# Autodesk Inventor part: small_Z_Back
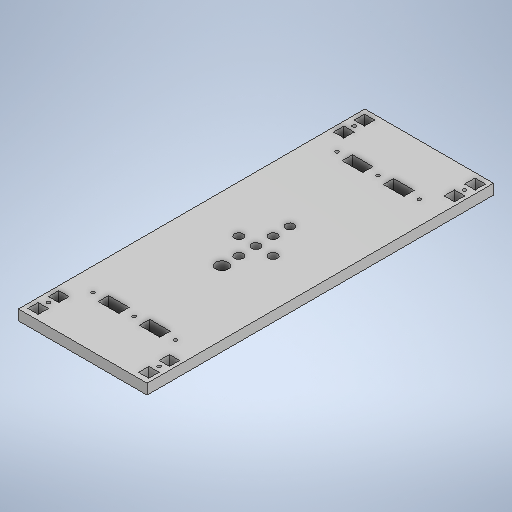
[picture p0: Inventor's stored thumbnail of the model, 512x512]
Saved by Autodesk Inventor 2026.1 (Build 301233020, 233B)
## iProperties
Created: 2026-10
Part Number: small_Z_Back
Material: Steel
Document SubType Name: Modeling
Designer: hp
Density: 7.85 g/cm^3
Appearance: Default
Author: hp
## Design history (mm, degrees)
feature "Body1"
sketch "Sketch1"
  geometry: L1 (19.089, 150.87)-(56.222, 150.87); L2 (56.222, 150.87)-(56.222, 50.004); L3 (56.222, 50.004)-(19.089, 50.004); L4 (19.089, 50.004)-(19.089, 150.87); 1 further point
  constraints: 8 end point, 2 parallel, 1 horizontal, 1 perpendicular
extrude "Extrusion1" join sketch "Sketch1" distance "d0" = 10; taper "d1" = 0 deg
sketch "Sketch2"
  geometry: L1 (0, 0)-(0, 202) reference; L2 (75, 202)-(75, 0) reference; C1 r 1 at (37.5, 172.244) reference; C2 r 2.5 at (37.5, 101); C3 r 2.5 at (37.5, 120.85); C4 r 2.5 at (37.5, 91); C5 r 2.5 at (47.5, 101); C6 r 3.6 at (37.5, 81.15); C7 r 2.5 at (37.5, 111); C8 r 2.5 at (27.5, 101); C9 r 2.5 at (37.5, 101); 4 further points
  constraints: 8 centre point, 5 vertical alignment, 3 horizontal alignment, 2 coincident, 1 concentric, 1 midpoint
  dimensions: "d6" = 5 diameter of C2; "d15" = 5 diameter of C4; "d16" = 5 diameter of C9; "d17" = 10 distance of point (37.5, 101) C5.centre; "d18" = 10 distance of point (37.5, 101) C8.centre; "d19" = 5 diameter of C8; "d20" = 5 diameter of C5; "d21" = 10 distance of point (37.5, 101) C7.centre; "d22" = 5 diameter of C7; "d23" = 7.2 diameter of C6; "d24" = 5 diameter of C3; "d25" = 10 distance of point (37.5, 101) C4.centre; "d26" = 9.85 distance of C7.centre C3.centre; "d27" = 9.85 distance of C4.centre C6.centre
extrude "Extrusion2" cut sketch "Sketch2" extent not by distance; stored distance "d12" = 0; taper "d13" = 0 deg
sketch "Sketch3"
  geometry: C1 r 4.5 at (37.5, -91); C2 r 2.5 at (37.5, -91) reference; C3 r 4.5 at (37.5, -120.85); C4 r 4.5 at (37.5, -111); C5 r 5.1 at (37.5, -81.15); C6 r 2.5 at (37.5, -120.85) reference; C7 r 2.5 at (37.5, -111) reference; C8 r 3.6 at (37.5, -81.15) reference; 1 further point
  constraints: 4 centre point, 4 concentric
  dimensions: "d28" = 9 diameter of C1; "d29" = 9 diameter of C3; "d30" = 9 diameter of C4; "d31" = 10.2 diameter of C5
extrude "Extrusion3" cut sketch "Sketch3" stored distance "d32" = 10; taper "d33" = 0 deg
body "Solid1"
